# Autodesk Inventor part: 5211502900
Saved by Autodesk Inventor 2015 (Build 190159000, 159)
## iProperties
Created: 2020-07
Part Number: 5211502900
Checked By: TraceParts S.A.
Material: Generic
Catalog Web Link: www.traceparts.com
Document SubType Name: Modeling
Designer: TraceParts
Density: 1 g/cm^3
Appearance: Default
Company: TraceParts S.A.
Author: TraceParts
REFERENCE: 5211502900
DESIGN: TDM-100 (230V 50) RE - 5211502900
SUPPLIER: Soler & Palau
TraceParts.PartNumber: 10-20122018-119657
TraceParts.PartTitle: TDM
TraceParts.InstanceId: 10-20122018-1196573ZHYDK5MBFLAGFAF6Y902W5OZ
TraceParts.PartStatus: Published
TraceParts.PartVersion: 1.0.2
TRACEPARTS: TRACEPARTS
TraceParts.PartLanguage: en
TraceParts.ClassPath: SOLER_PALAU:10-20122018-119657
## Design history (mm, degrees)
feature "5211502900"
body "Solid1"
